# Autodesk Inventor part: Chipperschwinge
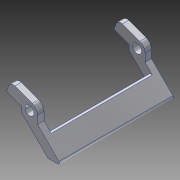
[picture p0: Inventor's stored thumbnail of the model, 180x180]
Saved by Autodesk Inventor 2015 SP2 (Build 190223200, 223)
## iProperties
Created: 2012-09
Part Number: Chipperschwinge
Material: Aluminium 6061
Document SubType Name: Modeling
Designer: rYan
Density: 2.71 g/cm^3
Mass: 13.5424 g
Surface Area: 33.3061 cm^2
Volume: 4.9972 cm^3
Appearance: Aluminium - flach
d0: 6,000 mm
d1: 45,00 grd
Author: rYan
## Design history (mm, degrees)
sketch "Skizze1"
  geometry: L1 (-8.485, 0)-(6.515, 15); L2 (16.515, 16.515)-(0, 0); L3 (0, 0)-(-8.485, 0); L4 (-17.112, 0)-(43.276, 0) reference; L5 (6.515, 15)-(6.515, 20); L6 (16.515, 16.515)-(16.515, 19.691); L7 (0, -5.938)-(0, 35.627) reference; L8 (11.515, 20)-(32.302, 27.566); L9 (23.518, 29.69)-(25.912, 23.112); L10 (25.912, 23.112)-(16.515, 19.691); L11 (23.518, 29.69)-(9.805, 24.698); L12 (11.515, 18)-(34.649, 18); L13 (11.515, 20)-(11.515, 18); A1 r 5 centre (11.515, 20) between (9.805, 24.698) and (6.515, 20)
  constraints: 22 end point, 3 vertical, 2 horizontal, 2 parallel, 2 point on circle, 1 centre point, 1 perpendicular, 1 point on line, 1 tangent
  dimensions: "d0" = 6 distance between parallel lines of L2 L1; "d1" = 45 deg angle of L3 L2; "d25" = 10 distance between parallel lines of L5 L6; "d28" = 20 distance from line of L4 L8.start; "d29" = 5 distance of L1.end L5.end; "d36" = 2 distance from line of L8.start L12; "d37" = 2 distance from line of L8.start L10; "d38" = 5 radius of A1; "d39" = 20 deg angle of L4 L10; "d40" = 10 distance of L9.end L6.end
extrude "Extrusion1" new body sketch "Skizze1" distance "d4" = 4; taper "d5" = 0 deg
sketch "Skizze2"
  geometry: L1 (8.485, 0)-(0, 0); L2 (0, 0)-(-3.5, 3.5); L3 (-3.5, 10.5)-(-2.015, 10.5); L4 (-2.015, 10.5)-(8.485, 0); L5 (-3.5, 6.5)-(-3.5, 3.5); L6 (-32.791, 0)-(15.365, 0) reference; L7 (-3.5, 6.5)-(-3.5, 10.5); L8 (0, 35.627)-(0, -5.938) reference; L9 (0, 0)-(-16.515, 16.515) reference; L10 (-3.5, 6.5)-(-3.5, 6.5); 1 other entity
  constraints: 14 end point, 2 horizontal, 2 parallel, 1 point on line, 1 vertical, 1 other
  dimensions: "d31" = 10.5 distance between parallel lines of L1 L3; "d44" = 45 deg angle of L6 L4; "d45" = 3 distance of L5.start L2.end; "d48" = 45 deg angle of L2 L1; "d51" = 0 distance of L5.start L7.start; "d52" = 3.5 distance between parallel lines of L8 L5
extrude "Extrusion2" join sketch "Skizze2" distance "d12" = 31.5; taper "d13" = 0 deg
mirror "Spiegeln1"
sketch "Skizze4"
  geometry: A1 r 5 centre (-11.515, -20) between (-9.805, -24.698) and (-6.515, -20) reference; 3 further points
  constraints: 2 coincident
hole "Bohrung1" sketch "Skizze4" at (-11.515, -20) diameter "d14" = 5.6; stored, may be unused: countersink angle "d18" = 90 deg, drill point angle "d20" = 118 deg; dims "d15" = 6, "d16" = 4, "d17" = 2, "d19" = 8
fillet "Rundung1" dims "d21" = 1
fillet "Rundung2" dims "d41" = 3
fillet "Rundung3" dims "d42" = 0.5
node "Volumenkörper1"
other parameters: "d22" = 5
